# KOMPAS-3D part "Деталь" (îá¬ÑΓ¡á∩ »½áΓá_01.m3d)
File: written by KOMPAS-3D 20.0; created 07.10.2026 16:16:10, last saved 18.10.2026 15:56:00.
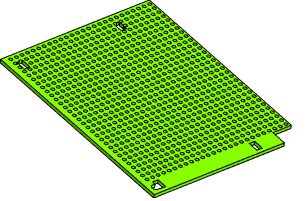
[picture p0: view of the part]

Document properties: Полное имя файла: D:\RicWork\Project-EPS32\box_compas\макетки\Макетная плата_01.m3d

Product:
- Part/product: Деталь
    Масса: 0.0509676

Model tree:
1. Эскиз:1
2. Элемент выдавливания:1
     Расстояние 1 = 1.5
3. Эскиз:2  (with: Элемент выдавливания:1)
4. Элемент выдавливания:2
     Расстояние 2 = 1.5
5. Эскиз:3  (with: Элемент выдавливания:1)
6. Элемент выдавливания:3
     Расстояние 2 = 1.5
7. Массив по сетке:1  (with: Элемент выдавливания:3, Эскиз:3, Элемент выдавливания:1)  (806 pattern instances)
     Шаг 1 = 2.54; Угол раствора = -90; Шаг 2 = 2.54
8. Эскиз:5  (with: Элемент выдавливания:1)
9. Элемент выдавливания:5
     Расстояние 2 = 1.5
10. Эскиз:8  (with: Элемент выдавливания:1, Элемент выдавливания:2)
11. Элемент выдавливания:10
     Расстояние 1 = 1.5
12. Массив по сетке:2  (with: Элемент выдавливания:10, Эскиз:8)  (4 pattern instances)
     Шаг 1 = 75.9; Угол раствора = -90; Шаг 2 = 44.2

Referenced files in D:\RicWork\Project-EPS32\box_compas\сборки компонентов\: ILI9341_86_50_DevBoard.a3d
